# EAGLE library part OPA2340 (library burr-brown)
Single-Supply, Rail-to-Rail Operational Amplifiers MicroAmplifier(TM) Series; Product Folder:OPA2340
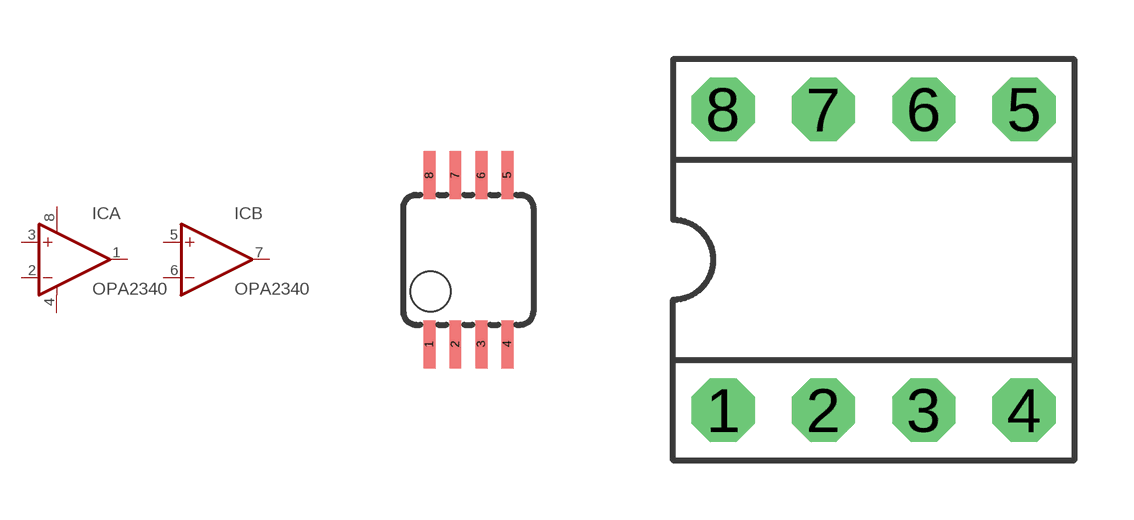
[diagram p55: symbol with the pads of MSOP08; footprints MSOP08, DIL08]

Designator prefix IC; gates A=OP-AMP+- B=OP-AMP

## OPA2340E (MF: TEXAS INSTRUMENTS; MPN: OPA2340EA/250; OC_FARNELL: 1101540; OC_NEWARK: 36K7580)  [MSOP08]
1  A:OUT  out
2  A:-IN  in
3  A:+IN  in
4  A:V-  pwr
5  B:+IN  in
6  B:-IN  in
7  B:OUT  out
8  A:V+  pwr

## OPA2340P (MF: TEXAS INSTRUMENTS; MPN: OPA2340PA; OC_FARNELL: 1129252; OC_NEWARK: 62K3460)  [DIL08]
Pads as for MSOP08

## OPA2340U (MF: TEXAS INSTRUMENTS; MPN: OPA2340UA; OC_FARNELL: 1101541; OC_NEWARK: 36K7581)  [SO08]
Pads as for MSOP08

## Footprint MSOP08 (pad centres in mm)
Mini Small Outline Package
smd 0.3 x 1.2: 1 -0.976,-2.113; 2 -0.326,-2.113; 3 0.324,-2.113; 4 0.974,-2.113; 5 0.974,2.112; 6 0.324,2.112; 7 -0.326,2.112; 8 -0.976,2.112

## Footprint DIL08 (pad centres in mm)
Dual In Line
drill 0.813 pad 1.6 octagon: 1 -3.81,-3.81; 2 -1.27,-3.81; 3 1.27,-3.81; 4 3.81,-3.81; 5 3.81,3.81; 6 1.27,3.81; 7 -1.27,3.81; 8 -3.81,3.81

## Footprint SO08 (pad centres in mm)
Small Outline Package
smd 0.61 x 2.21: 1 -1.905,-2.616; 2 -0.635,-2.616; 3 0.635,-2.616; 4 1.905,-2.616; 5 1.905,2.616; 6 0.635,2.616; 7 -0.635,2.616; 8 -1.905,2.616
